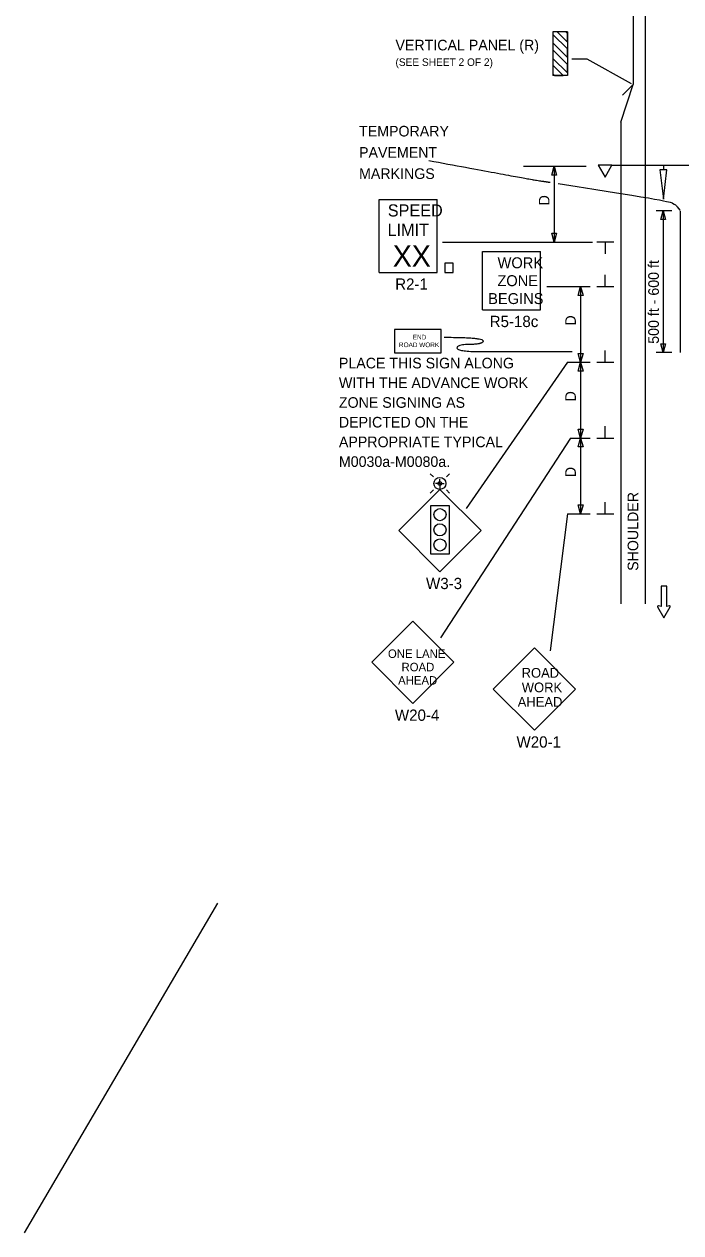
# Model space of a CAD drawing. Extents: x 16520 to 18479, y 5662 to 6927.
# Drawn here: x 16520 to 16953, y 5662 to 6460 of the extents above; entities that cross this region are included whole.
import ezdxf

# ---------------------------------------------------------------- set-up
doc = ezdxf.new("R2010")
doc.units = 0
for name, color, linetype in [('ALI_LEGAL_EX', 7, 'Continuous'), ('MT_SCRATCH_LEVEL_E', 7, 'Continuous'), ('PAVT_EDGE_EX', 7, 'Continuous'), ('TRAFFIC_SIGNS_PR', 7, 'Continuous'), ('TYPICAL_TEXT_DIMEN_PR', 7, 'Continuous')]:
    doc.layers.add(name, color=color, linetype=linetype)

msp = doc.modelspace()

# ---------------------------------------------------------------- linework, layer by layer
at = {"layer": 'ALI_LEGAL_EX'}
msp.add_lwpolyline([(16952.78, 6336.76), (16952.78, 6243.13)], dxfattribs=at)
at = {"layer": 'MT_SCRATCH_LEVEL_E'}
for p, q in [((16943.98, 6089.01), (16940.24, 6089.01)), ((16940.24, 6089.01), (16940.24, 6075.76)), ((16943.98, 6089.01), (16940.24, 6089.01)), ((16940.24, 6089.01), (16940.24, 6075.76)), ((16943.98, 6075.76), (16943.98, 6089.01)), ((16943.98, 6075.76), (16943.98, 6089.01)), ((16940.24, 6075.76), (16938.46, 6076.07)), ((16940.24, 6075.76), (16938.46, 6076.07)), ((16945.76, 6076.07), (16943.98, 6075.76)), ((16945.76, 6076.07), (16943.98, 6075.76)), ((16937.98, 6075.39), (16942.13, 6068.15)), ((16937.98, 6075.39), (16942.13, 6068.15)), ((16942.13, 6068.15), (16946.24, 6075.39)), ((16942.13, 6068.15), (16946.24, 6075.39))]:
    msp.add_line(p, q, dxfattribs=at)
for centre, start, end in [((16938.39, 6075.61), 80.03619, 209.77312), ((16938.39, 6075.61), 80.03619, 209.77312), ((16945.83, 6075.61), 330.42484, 99.96381), ((16945.83, 6075.61), 330.42484, 99.96381)]:
    msp.add_arc(centre, 0.463, start, end, dxfattribs=at)
at = {"layer": 'PAVT_EDGE_EX'}
for p, q in [((16929.78, 6899.43), (16929.78, 6077.5)), ((16921.78, 6551.35), (16921.78, 6419.96)), ((16913.78, 6395.26), (16921.78, 6419.96)), ((16921.78, 6419.96), (16914.71, 6412.89)), ((16913.78, 6395.26), (16913.78, 6077.5))]:
    msp.add_line(p, q, dxfattribs=at)
at = {"layer": 'TRAFFIC_SIGNS_PR'}
for p, q in [((16878.5, 6454.77), (16868.9, 6454.77)), ((16868.9, 6454.77), (16868.9, 6425.97)), ((16878.5, 6454.77), (16868.9, 6454.77)), ((16868.9, 6454.77), (16868.9, 6425.97)), ((16878.5, 6443.5), (16868.9, 6453.1)), ((16878.5, 6443.5), (16868.9, 6453.1)), ((16878.5, 6448.02), (16871.76, 6454.77)), ((16878.5, 6448.02), (16871.76, 6454.77)), ((16878.5, 6453.68), (16877.41, 6454.77)), ((16878.5, 6453.68), (16877.41, 6454.77)), ((16878.5, 6454.77), (16878.5, 6425.97)), ((16878.5, 6454.77), (16878.5, 6425.97)), ((16878.5, 6437.84), (16868.9, 6447.44)), ((16878.5, 6437.84), (16868.9, 6447.44)), ((16878.5, 6433.32), (16868.9, 6442.92)), ((16878.5, 6433.32), (16868.9, 6442.92)), ((16878.5, 6427.66), (16868.9, 6437.26)), ((16878.5, 6427.66), (16868.9, 6437.26)), ((16875.67, 6425.97), (16868.9, 6432.73)), ((16875.67, 6425.97), (16868.9, 6432.73)), ((16870.01, 6425.97), (16868.9, 6427.08)), ((16870.01, 6425.97), (16868.9, 6427.08)), ((16878.5, 6425.97), (16868.9, 6425.97)), ((16878.5, 6425.97), (16868.9, 6425.97)), ((16907.78, 6366.76), (16999.78, 6366.76)), ((16941.78, 6366.76), (16941.78, 6363.74)), ((16754.2, 6344.1), (16792.6, 6344.1)), ((16754.2, 6296.1), (16754.2, 6344.1)), ((16792.6, 6296.1), (16792.6, 6344.1)), ((16822.4, 6271.44), (16822.4, 6309.84)), ((16822.4, 6309.84), (16860.8, 6309.84)), ((16860.8, 6271.44), (16860.8, 6309.84)), ((16754.2, 6296.1), (16792.6, 6296.1)), ((16822.4, 6271.44), (16860.8, 6271.44)), ((16790.06, 6161.1), (16788.02, 6163.14)), ((16794.34, 6156.82), (16791.46, 6156.82)), ((16794.34, 6156.82), (16794.34, 6159.7)), ((16794.34, 6156.82), (16794.34, 6152.88)), ((16794.34, 6156.82), (16797.21, 6156.82)), ((16798.62, 6161.1), (16800.65, 6163.14)), ((16794.34, 6152.88), (16767.18, 6125.73)), ((16790.06, 6152.54), (16788.02, 6150.51)), ((16821.49, 6125.73), (16794.34, 6152.88)), ((16800.65, 6150.51), (16798.62, 6152.54)), ((16767.18, 6125.73), (16794.34, 6098.58)), ((16794.34, 6098.58), (16821.49, 6125.73)), ((16776.51, 6066.01), (16749.36, 6038.85)), ((16803.66, 6038.85), (16776.51, 6066.01)), ((16856.73, 6048.33), (16829.58, 6021.18)), ((16883.88, 6021.18), (16856.73, 6048.33)), ((16749.36, 6038.85), (16776.51, 6011.7)), ((16776.51, 6011.7), (16803.66, 6038.85)), ((16829.58, 6021.18), (16856.73, 5994.02)), ((16856.73, 5994.02), (16883.88, 6021.18))]:
    msp.add_line(p, q, dxfattribs=at)
for points in [[(16878.5, 6443.5), (16868.9, 6453.1), (16868.9, 6447.44), (16878.5, 6437.84)], [(16878.5, 6443.5), (16868.9, 6453.1), (16868.9, 6447.44), (16878.5, 6437.84)], [(16877.41, 6454.77), (16871.76, 6454.77), (16878.5, 6448.02), (16878.5, 6453.68)], [(16877.41, 6454.77), (16871.76, 6454.77), (16878.5, 6448.02), (16878.5, 6453.68)], [(16878.5, 6433.32), (16868.9, 6442.92), (16868.9, 6437.26), (16878.5, 6427.66)], [(16878.5, 6433.32), (16868.9, 6442.92), (16868.9, 6437.26), (16878.5, 6427.66)], [(16868.9, 6432.73), (16868.9, 6427.08), (16870.01, 6425.97), (16875.67, 6425.97)], [(16868.9, 6432.73), (16868.9, 6427.08), (16870.01, 6425.97), (16875.67, 6425.97)], [(16898.78, 6366.76), (16903.28, 6358.97), (16907.78, 6366.76)], [(16939.53, 6363.74), (16941.78, 6344.32), (16944.03, 6363.74)], [(16797.61, 6296.1), (16803.21, 6296.1), (16803.21, 6302.27), (16797.61, 6302.27)], [(16764.44, 6242.96), (16795.16, 6242.96), (16795.16, 6258.32), (16764.44, 6258.32)], [(16800.4, 6110.27), (16788.4, 6110.27), (16788.4, 6142.27), (16800.4, 6142.27)]]:
    msp.add_lwpolyline(points, close=True, dxfattribs=at)
for centre, radius in [((16794.34, 6156.82), 3.94), ((16794.34, 6156.82), 1.28), ((16794.4, 6136.27), 4), ((16794.4, 6126.27), 4), ((16794.4, 6116.27), 4)]:
    msp.add_circle(centre, radius, dxfattribs=at)
at = {"layer": 'TYPICAL_TEXT_DIMEN_PR'}
for p, q in [((16891.56, 6436.77), (16881.31, 6436.77)), ((16891.56, 6436.77), (16881.31, 6436.77)), ((16920.82, 6420.54), (16891.56, 6436.77)), ((16920.82, 6420.54), (16891.56, 6436.77)), ((16849.43, 6366.06), (16890.78, 6366.06)), ((16868.21, 6360.2), (16869.78, 6366.06)), ((16869.78, 6366.06), (16869.78, 6316.06)), ((16869.78, 6366.06), (16871.35, 6360.2)), ((16869.78, 6360.2), (16868.21, 6360.2)), ((16871.35, 6360.2), (16869.78, 6360.2)), ((16950.89, 6339.42), (16952.6, 6337.06)), ((16947.46, 6336.76), (16936.94, 6336.76)), ((16940.05, 6330.9), (16941.62, 6336.76)), ((16941.62, 6336.76), (16941.62, 6243.13)), ((16941.62, 6336.76), (16943.19, 6330.9)), ((16941.62, 6330.9), (16940.05, 6330.9)), ((16943.19, 6330.9), (16941.62, 6330.9)), ((16796.1, 6316.06), (16895.07, 6316.06)), ((16869.78, 6316.06), (16868.21, 6321.92)), ((16868.21, 6321.92), (16869.78, 6321.92)), ((16869.78, 6321.92), (16871.35, 6321.92)), ((16871.35, 6321.92), (16869.78, 6316.06)), ((16909.03, 6316.06), (16897.78, 6316.06)), ((16903.41, 6316.06), (16903.41, 6308.28)), ((16903.41, 6286.76), (16903.41, 6294.55)), ((16864.86, 6286.76), (16893.53, 6286.76)), ((16885.64, 6280.9), (16887.21, 6286.76)), ((16887.21, 6286.76), (16887.21, 6236.76)), ((16887.21, 6286.76), (16888.78, 6280.9)), ((16897.78, 6286.76), (16909.03, 6286.76)), ((16887.21, 6280.9), (16885.64, 6280.9)), ((16888.78, 6280.9), (16887.21, 6280.9)), ((16903.41, 6236.76), (16903.41, 6244.55)), ((16941.62, 6243.13), (16940.05, 6249)), ((16940.05, 6249), (16941.62, 6249)), ((16941.62, 6249), (16943.19, 6249)), ((16943.19, 6249), (16941.62, 6243.13)), ((16878.62, 6236.76), (16811.58, 6140.36)), ((16878.62, 6236.76), (16893.53, 6236.76)), ((16887.21, 6236.76), (16885.64, 6242.63)), ((16885.64, 6242.63), (16887.21, 6242.63)), ((16885.64, 6230.9), (16887.21, 6236.76)), ((16887.21, 6242.63), (16888.78, 6242.63)), ((16888.78, 6242.63), (16887.21, 6236.76)), ((16887.21, 6236.76), (16887.21, 6186.76)), ((16887.21, 6236.76), (16888.78, 6230.9)), ((16897.78, 6236.76), (16909.03, 6236.76)), ((16947.46, 6243.13), (16936.94, 6243.13)), ((16887.21, 6230.9), (16885.64, 6230.9)), ((16888.78, 6230.9), (16887.21, 6230.9)), ((16887.21, 6186.76), (16885.64, 6192.63)), ((16885.64, 6192.63), (16887.21, 6192.63)), ((16887.21, 6192.63), (16888.78, 6192.63)), ((16888.78, 6192.63), (16887.21, 6186.76)), ((16903.41, 6186.76), (16903.41, 6194.55)), ((16880.53, 6186.76), (16794.74, 6054.94)), ((16880.53, 6186.76), (16893.53, 6186.76)), ((16885.64, 6180.9), (16887.21, 6186.76)), ((16887.21, 6180.9), (16885.64, 6180.9)), ((16887.21, 6186.76), (16887.21, 6136.76)), ((16887.21, 6186.76), (16888.78, 6180.9)), ((16888.78, 6180.9), (16887.21, 6180.9)), ((16897.78, 6186.76), (16909.03, 6186.76)), ((16887.21, 6136.76), (16885.64, 6142.63)), ((16885.64, 6142.63), (16887.21, 6142.63)), ((16887.21, 6142.63), (16888.78, 6142.63)), ((16888.78, 6142.63), (16887.21, 6136.76)), ((16903.41, 6136.76), (16903.41, 6144.55)), ((16878.62, 6136.76), (16867, 6046.37)), ((16878.62, 6136.76), (16893.53, 6136.76)), ((16897.78, 6136.76), (16909.03, 6136.76)), ((16647.75, 5880), (16520.14, 5662.47))]:
    msp.add_line(p, q, dxfattribs=at)
for points, degree in [([(16787.14, 6369.89), (16852.52, 6357.73), (16860.07, 6356.58), (16867.03, 6355.51)], 2), ([(16872.42, 6354.67), (16943.06, 6343.72), (16949.06, 6341.58), (16950.77, 6339.57), (16950.81, 6339.52), (16950.85, 6339.47), (16950.89, 6339.42)], 3), ([(16797.27, 6253.26), (16822.86, 6253.26), (16822.86, 6248.55), (16805.64, 6248.55), (16805.64, 6243.84), (16838.64, 6243.84), (16881.57, 6243.84)], 2)]:
    msp.add_open_spline(points, degree=degree, dxfattribs=at)

# ---------------------------------------------------------------- texts
at = {"layer": 'TRAFFIC_SIGNS_PR'}
for s, height, p in [('SPEED', 8, (16759.96, 6332.96)), ('LIMIT', 8, (16759.8, 6320.16)), ('XX', 14.031, (16763.31, 6299.86)), ('WORK', 7.217, (16832.4, 6298.81)), ('R2-1', 7.44, (16764.87, 6284.66)), ('ZONE', 7.217, (16832.28, 6287)), ('BEGINS', 7.217, (16826.21, 6275.19)), ('R5-18c', 7.44, (16827.21, 6260)), ('END', 3.065, (16776.44, 6251.86)), ('ROAD WORK', 3.065, (16767.33, 6246.76)), ('PLACE THIS SIGN ALONG', 7, (16727.75, 6232.75)), ('WITH THE ADVANCE WORK', 7, (16727.75, 6219.75)), ('ZONE SIGNING AS', 7, (16727.75, 6206.75)), ('DEPICTED ON THE', 7, (16727.75, 6193.75)), ('APPROPRIATE TYPICAL', 7, (16727.75, 6180.75)), ('M0030a-M0080a.', 7, (16727.75, 6167.75)), ('W3-3', 7.44, (16785.21, 6087.14)), ('ONE LANE', 5.6, (16760.1, 6041.72)), ('ROAD', 5.6, (16769.05, 6032.92)), ('AHEAD', 5.6, (16766.8, 6024.12)), ('ROAD', 6.4, (16848.27, 6028.71)), ('WORK', 6.4, (16848.38, 6019.11)), ('AHEAD', 6.4, (16845.69, 6009.51)), ('W20-4', 7.44, (16764.69, 6000.26)), ('W20-1', 7.44, (16844.9, 5982.58))]:
    msp.add_text(s, height=height, dxfattribs=at).set_placement(p)
at = {"layer": 'TYPICAL_TEXT_DIMEN_PR'}
for s, height, p in [('VERTICAL PANEL (R)', 7, (16765.06, 6442.54)), ('VERTICAL PANEL (R)', 7, (16765.06, 6442.54)), ('(SEE SHEET 2 OF 2)', 5, (16765.06, 6432.28)), ('(SEE SHEET 2 OF 2)', 5, (16765.06, 6432.28)), ('TEMPORARY', 7, (16741.04, 6385.74)), ('PAVEMENT', 7, (16741.04, 6371.74)), ('MARKINGS', 7, (16741.04, 6357.74))]:
    msp.add_text(s, height=height, dxfattribs=at).set_placement(p)
for s, p in [('D', (16866.65, 6340.28)), ('500 ft - 600 ft', (16938.8, 6248.99)), ('D', (16884.07, 6260.98)), ('D', (16884.07, 6210.98)), ('D', (16884.07, 6160.98)), ('SHOULDER', (16925.2, 6099.18))]:
    msp.add_text(s, height=7, rotation=90, dxfattribs=at).set_placement(p)

doc.saveas('drawing.dxf')
